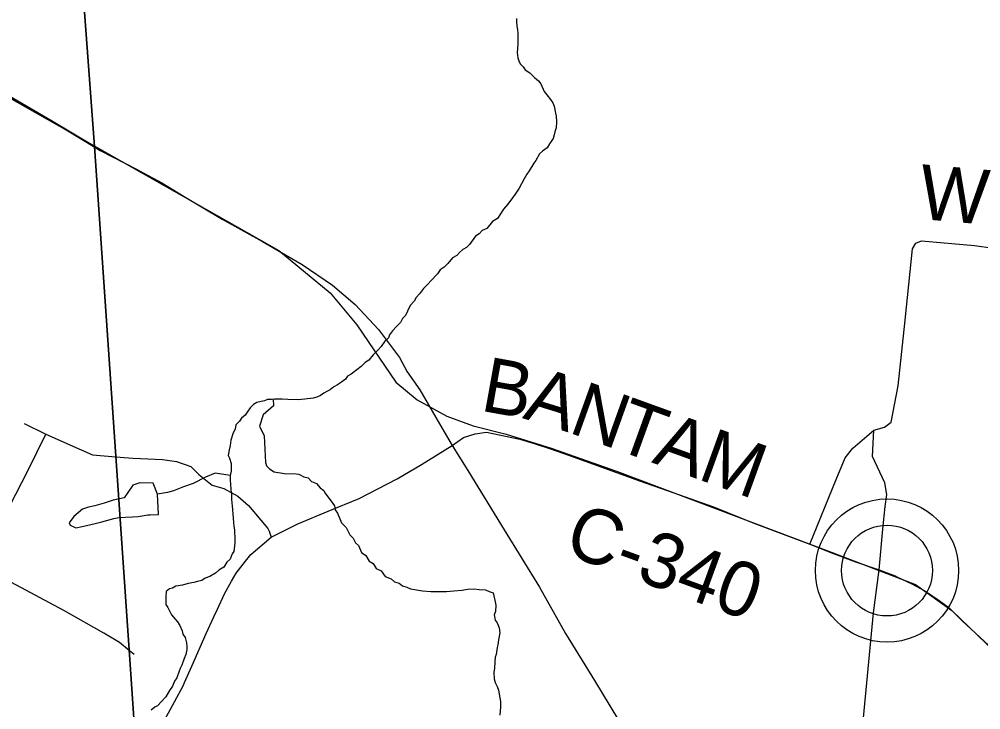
# Model space of a CAD drawing. Extents: x 0 to 39.3, y -3.9 to 22.
# Drawn here: x 7.624 to 8.623, y 16.123 to 16.84 of the extents above; entities that cross this region are included whole.
import ezdxf

# ---------------------------------------------------------------- set-up
doc = ezdxf.new("R2010")
doc.units = 0
for name, color, linetype in [('GM_X_Corporation', 7, 'Continuous'), ('GM_X_County_Road', 7, 'Continuous'), ('GM_X_County_Road_Text', 7, 'Continuous'), ('GM_X_Minor_Lake', 7, 'Continuous'), ('GM_X_Minor_River', 7, 'Continuous'), ('GM_X_Rail_Line', 7, 'Continuous'), ('GM_X_State_Route', 7, 'Continuous'), ('GM_X_Township_Road', 7, 'Continuous'), ('GM_X_Unincorporated', 7, 'Continuous'), ('GM_X_Unincorporated_Location', 7, 'Continuous')]:
    doc.layers.add(name, color=color, linetype=linetype)

msp = doc.modelspace()

# ---------------------------------------------------------------- linework, layer by layer
at = {"layer": 'GM_X_Corporation'}
for points in [[(7.60466, 16.76574), (7.6579, 16.73471), (7.70243, 16.70782), (7.66327, 17.23426), (8.7, 17.13724), (8.7, 20.7)], [(7.83678, 14.75308), (7.74674, 16.06315), (7.73835, 16.18516), (7.72454, 16.38622), (7.70243, 16.70782), (7.6579, 16.73471), (7.60466, 16.76574)]]:
    msp.add_lwpolyline(points, dxfattribs=at)
msp.add_lwpolyline([(7.89397, 13.9), (8.7, 13.9), (8.7, 17.13724), (7.66327, 17.23426), (7.70243, 16.70782), (7.72454, 16.38622), (7.73835, 16.18516), (7.74674, 16.06315), (7.83678, 14.75308), (7.8533, 14.49864), (7.86853, 14.2638)], close=True, dxfattribs=at)
at = {"layer": 'GM_X_County_Road'}
for points in [[(8.44541, 16.29495), (8.47264, 16.36211), (8.48225, 16.38452), (8.49002, 16.39458), (8.51197, 16.41333), (8.52306, 16.41653), (8.52981, 16.42157), (8.53713, 16.45953), (8.54445, 16.52768), (8.5522, 16.60154), (8.55564, 16.60753), (8.56134, 16.60981), (8.61651, 16.60523), (8.65582, 16.59954), (8.7, 16.59435)], [(8.07381, 16.39756), (8.08571, 16.40556), (8.09782, 16.40967), (8.10961, 16.41116), (8.14414, 16.40396), (8.15912, 16.39938), (8.17512, 16.39435), (8.18203, 16.39185)], [(8.51747, 16.26835), (8.52121, 16.31062), (8.5236, 16.33388), (8.52524, 16.34655), (8.52341, 16.35845), (8.5106, 16.38589), (8.51197, 16.41333)], [(8.18203, 16.39185), (8.1909, 16.38863), (8.22063, 16.37811), (8.26854, 16.3607), (8.30433, 16.34839), (8.34549, 16.33375), (8.38712, 16.31683), (8.44541, 16.29495), (8.46624, 16.28664)], [(8.46624, 16.28664), (8.49277, 16.27658), (8.51747, 16.26835), (8.53393, 16.26194), (8.53566, 16.26112)], [(8.48594, 15.95462), (8.51168, 16.22373), (8.51747, 16.26835)], [(8.53566, 16.26112), (8.55131, 16.25371), (8.56503, 16.2464), (8.57875, 16.23724), (8.58973, 16.22902), (8.60391, 16.21484), (8.63547, 16.18602), (8.7, 16.12481)]]:
    msp.add_lwpolyline(points, dxfattribs=at)
at = {"layer": 'GM_X_Minor_Lake'}
for points in [[(7.76779, 16.34686), (7.76344, 16.35834), (7.74939, 16.35858), (7.74214, 16.35605), (7.73707, 16.34854), (7.73318, 16.3429), (7.72175, 16.34044), (7.71259, 16.33756), (7.70267, 16.33469), (7.69619, 16.33329), (7.69008, 16.33111), (7.68084, 16.32367), (7.67617, 16.31691), (7.67727, 16.31461), (7.68292, 16.31185), (7.68978, 16.31325), (7.70312, 16.31643), (7.70998, 16.31822), (7.72256, 16.32142), (7.7279, 16.32246), (7.74196, 16.32336), (7.74766, 16.32364), (7.75184, 16.32433), (7.75793, 16.32536), (7.76021, 16.32532)], [(7.76021, 16.32532), (7.76908, 16.32567), (7.76779, 16.34686)]]:
    msp.add_lwpolyline(points, dxfattribs=at)
at = {"layer": 'GM_X_Minor_River'}
for points in [[(8.14079, 16.84104), (8.14074, 16.838), (8.14104, 16.83305), (8.14174, 16.82961), (8.14205, 16.82542), (8.14231, 16.81819), (8.14226, 16.81515), (8.14178, 16.80945), (8.14134, 16.80565), (8.142, 16.79994), (8.14309, 16.79688), (8.14456, 16.79381), (8.14755, 16.79071), (8.14978, 16.78763), (8.15467, 16.7845), (8.15953, 16.77947), (8.16365, 16.77597), (8.16588, 16.77289), (8.16955, 16.76522), (8.17215, 16.76175), (8.17625, 16.75673), (8.17847, 16.75327), (8.17994, 16.74982), (8.18133, 16.74257), (8.18204, 16.73951), (8.18232, 16.73342), (8.18184, 16.72734), (8.18063, 16.72318), (8.17982, 16.72015), (8.17899, 16.71636), (8.17509, 16.71072), (8.17274, 16.70658), (8.16775, 16.70324), (8.16465, 16.70025), (8.16074, 16.69348), (8.15879, 16.69047), (8.15409, 16.68256), (8.15137, 16.67918), (8.14863, 16.67429), (8.14352, 16.66449), (8.13924, 16.65847), (8.13651, 16.65472), (8.13184, 16.64795), (8.12719, 16.64271), (8.12095, 16.63331), (8.11595, 16.62997), (8.11012, 16.62285), (8.10515, 16.62065), (8.10205, 16.61728), (8.0982, 16.61468)], [(8.0982, 16.61468), (8.09197, 16.60604), (8.08888, 16.60306), (8.08504, 16.60084), (8.08196, 16.59823), (8.07886, 16.59486), (8.07425, 16.59228), (8.06959, 16.58628), (8.06573, 16.58254), (8.0615, 16.57995), (8.05877, 16.57581), (8.0518, 16.56833), (8.0487, 16.56496), (8.04406, 16.56047), (8.04016, 16.55484), (8.03668, 16.55109), (8.03433, 16.54733), (8.03046, 16.54283), (8.02769, 16.5368), (8.02534, 16.53227), (8.02225, 16.52928), (8.02028, 16.52513), (8.01602, 16.52102), (8.01215, 16.51653), (8.00904, 16.5124), (8.00784, 16.50937), (8.00398, 16.50564), (8.00009, 16.50038), (7.99698, 16.49663), (7.99195, 16.49139), (7.9873, 16.48615), (7.98346, 16.48355), (7.97959, 16.47944), (7.97497, 16.47609), (7.96919, 16.47163), (7.96535, 16.46941), (7.96302, 16.46641), (7.95916, 16.46305), (7.95494, 16.46047), (7.9511, 16.45825), (7.94763, 16.45565), (7.94072, 16.45158), (7.93726, 16.44936), (7.93343, 16.44753), (7.92961, 16.44645), (7.92085, 16.44547), (7.91399, 16.44483), (7.90335, 16.44501), (7.89728, 16.4455), (7.88929, 16.44564), (7.88625, 16.44531), (7.88206, 16.445), (7.879, 16.44392), (7.87557, 16.44322), (7.87099, 16.44215), (7.86753, 16.43993), (7.86405, 16.43657), (7.86171, 16.43319), (7.85898, 16.42905), (7.85512, 16.42569), (7.85317, 16.42268), (7.8493, 16.41895), (7.84847, 16.4144), (7.8465, 16.41063), (7.8441, 16.40306), (7.84324, 16.39737), (7.8424, 16.39282), (7.84117, 16.38714), (7.84259, 16.38406), (7.84441, 16.37883)], [(7.8882, 16.44552), (7.88844, 16.43842), (7.87764, 16.4291), (7.87371, 16.41741), (7.87879, 16.40742), (7.87991, 16.37964)], [(7.84441, 16.37883), (7.84426, 16.37083), (7.84342, 16.36628), (7.84332, 16.36095), (7.84364, 16.35752), (7.84391, 16.35143), (7.8446, 16.34723), (7.84487, 16.34114), (7.84551, 16.33427), (7.84583, 16.33122), (7.84612, 16.32589), (7.84643, 16.32246), (7.84671, 16.31674), (7.84704, 16.31407), (7.84772, 16.30949), (7.84805, 16.30682), (7.84836, 16.30263), (7.84824, 16.29616), (7.8478, 16.29312), (7.84732, 16.28742), (7.84537, 16.28479), (7.84337, 16.2795), (7.83988, 16.27613), (7.83674, 16.27086), (7.83174, 16.2679), (7.82826, 16.26491), (7.8221, 16.26121), (7.81751, 16.25976), (7.81404, 16.25716), (7.80945, 16.2561), (7.80562, 16.25502), (7.79989, 16.25398), (7.79377, 16.25218), (7.7869, 16.25115), (7.78344, 16.24931), (7.78038, 16.2486), (7.7769, 16.24562), (7.77643, 16.2403), (7.77666, 16.2323), (7.77851, 16.22922), (7.78108, 16.22423), (7.78256, 16.22154), (7.78852, 16.21421), (7.79111, 16.21035), (7.79368, 16.20498), (7.79438, 16.20154), (7.7966, 16.19808), (7.79802, 16.19235), (7.79834, 16.18891), (7.79827, 16.18549), (7.79742, 16.18018), (7.79544, 16.17602), (7.79303, 16.16921), (7.79145, 16.16581), (7.79026, 16.16317), (7.78784, 16.15598), (7.7855, 16.15259), (7.7835, 16.1473), (7.78037, 16.14278), (7.77645, 16.13638), (7.77217, 16.1315), (7.76791, 16.12701), (7.76521, 16.12554), (7.76135, 16.12256)], [(7.87991, 16.37964), (7.88098, 16.3762), (7.88435, 16.3731), (7.88925, 16.36997), (7.89987, 16.36826), (7.91205, 16.36805), (7.91471, 16.36763), (7.91999, 16.36487), (7.92453, 16.36365), (7.9279, 16.36017), (7.93318, 16.35779), (7.93691, 16.35354), (7.94067, 16.35081), (7.94176, 16.34813), (7.94734, 16.3408), (7.9518, 16.33464), (7.95248, 16.33043), (7.9547, 16.32697), (7.95909, 16.317), (7.96395, 16.31235), (7.96762, 16.30467), (7.97098, 16.30119), (7.97356, 16.2962), (7.97656, 16.29348), (7.97985, 16.28619), (7.98436, 16.28307), (7.98768, 16.2773), (7.99183, 16.27495), (7.99516, 16.26956), (8.00006, 16.26719), (8.00452, 16.26141), (8.01057, 16.25902), (8.01394, 16.25592), (8.01886, 16.25431), (8.02224, 16.25159), (8.02678, 16.25037), (8.03055, 16.2484), (8.03701, 16.24753), (8.04308, 16.24628), (8.05182, 16.24575), (8.05905, 16.24562), (8.06819, 16.24585), (8.07582, 16.24648), (8.08421, 16.2471), (8.08993, 16.24814), (8.09679, 16.2484), (8.10211, 16.24793), (8.10857, 16.24744), (8.11235, 16.24585), (8.11651, 16.24426), (8.11863, 16.23509), (8.11933, 16.23165), (8.11882, 16.22481), (8.11762, 16.2214), (8.11866, 16.21605), (8.12052, 16.21336), (8.1227, 16.20799), (8.12337, 16.20265), (8.1221, 16.19544), (8.12125, 16.19051), (8.12081, 16.18747), (8.11954, 16.18026), (8.11873, 16.17761), (8.11827, 16.17305), (8.11776, 16.16582), (8.11731, 16.16202), (8.11756, 16.15517), (8.11864, 16.15134), (8.12084, 16.14712), (8.12192, 16.14329), (8.12329, 16.13528), (8.12399, 16.13146), (8.12427, 16.12612), (8.12335, 16.11739)], [(7.84342, 16.36628), (7.82776, 16.36861), (7.81783, 16.36461), (7.80481, 16.35799), (7.79487, 16.35436), (7.78456, 16.35036), (7.77845, 16.34857), (7.76779, 16.34686)]]:
    msp.add_lwpolyline(points, dxfattribs=at)
at = {"layer": 'GM_X_Rail_Line'}
msp.add_lwpolyline([(7.57788, 16.77877), (7.89409, 16.59986), (7.94728, 16.55608), (7.97489, 16.52279), (8.01544, 16.46306), (8.0377, 16.44475), (8.06826, 16.42779), (8.09576, 16.41773), (8.13011, 16.40916), (8.17679, 16.39479), (8.24457, 16.37069), (8.46874, 16.28619), (8.55532, 16.25293), (8.59277, 16.22593), (8.7, 16.12327)], dxfattribs=at)
at = {"layer": 'GM_X_State_Route'}
for points in [[(7.4893, 16.81722), (7.51737, 16.80767), (7.53663, 16.80049), (7.56603, 16.78677), (7.60489, 16.76521), (7.65813, 16.73419), (7.70266, 16.7073), (7.70842, 16.70382), (7.74599, 16.68455), (7.75367, 16.68038)], [(7.75367, 16.68038), (7.77244, 16.67018), (7.79563, 16.65613), (7.83515, 16.63261), (7.87695, 16.6091), (7.91811, 16.58526), (7.94978, 16.56403), (7.9733, 16.54378), (7.99747, 16.51798), (8.01935, 16.48891), (8.02737, 16.47401), (8.04026, 16.45508), (8.06077, 16.42001), (8.07381, 16.39756)], [(7.79601, 16.15107), (7.80347, 16.16818), (7.81856, 16.20204), (7.8265, 16.21943), (7.83008, 16.22738), (7.83738, 16.24329), (7.84473, 16.2565), (7.84954, 16.26476), (7.85929, 16.27736), (7.865, 16.28412), (7.88604, 16.30211), (7.91357, 16.31604), (7.9453, 16.3293), (7.97746, 16.34222), (8.01675, 16.3628), (8.04226, 16.37766), (8.07381, 16.39756)], [(8.07381, 16.39756), (8.09032, 16.37156), (8.12793, 16.30965), (8.16461, 16.25032), (8.1917, 16.20198), (8.22178, 16.15321), (8.2548, 16.09881), (8.27418, 16.06819), (8.29117, 16.04668), (8.30299, 16.03576), (8.3115, 16.02725), (8.32563, 16.01439), (8.3423, 16.00261), (8.35607, 15.99391), (8.37219, 15.98485), (8.38705, 15.97834), (8.40064, 15.9729), (8.42092, 15.96601), (8.4481, 15.9604), (8.48594, 15.95462)], [(7.63346, 15.94077), (7.64241, 15.94836), (7.66403, 15.96893), (7.68759, 15.98994), (7.70785, 16.0111), (7.72556, 16.03331), (7.74043, 16.05253), (7.74697, 16.06263), (7.74958, 16.06663), (7.76143, 16.08585), (7.76924, 16.10131), (7.78562, 16.1313), (7.79483, 16.14837), (7.79601, 16.15107)]]:
    msp.add_lwpolyline(points, dxfattribs=at)
at = {"layer": 'GM_X_Township_Road'}
for p, q in [((7.62932, 16.4201), (7.65197, 16.40902)), ((7.65197, 16.40902), (7.68854, 16.393))]:
    msp.add_line(p, q, dxfattribs=at)
for points in [[(7.74383, 16.18046), (7.73859, 16.18464), (7.72842, 16.19274), (7.71223, 16.20238), (7.67051, 16.22616), (7.59123, 16.2683), (7.58619, 16.2741), (7.58908, 16.28543), (7.63318, 16.37119), (7.65197, 16.40902)], [(7.68854, 16.393), (7.70042, 16.38779), (7.72477, 16.38569), (7.73771, 16.38458)], [(7.73771, 16.38458), (7.74269, 16.38415), (7.77307, 16.38284), (7.78759, 16.38085), (7.80246, 16.37557), (7.81071, 16.36731), (7.82458, 16.35609), (7.83678, 16.35256), (7.85149, 16.3446), (7.86245, 16.335), (7.87506, 16.3197), (7.88255, 16.31128), (7.88406, 16.30858), (7.88604, 16.30211)]]:
    msp.add_lwpolyline(points, dxfattribs=at)
at = {"layer": 'GM_X_Unincorporated'}
for radius in [0.0744, 0.04716]:
    msp.add_circle((8.52559, 16.26751), radius, dxfattribs=at)
at = {"layer": 'GM_X_Unincorporated_Location'}
msp.add_line((8.52559, 16.26751), (8.52559, 16.26751), dxfattribs=at)

# ---------------------------------------------------------------- texts
at = {"layer": 'GM_X_County_Road_Text'}
for s, height, rotation, p in [('W', 0.05682, 355.06082, (8.55733, 16.63287)), ('B', 0.05682, 349.7908, (8.10206, 16.43378)), ('A', 0.05682, 342.82135, (8.14622, 16.42594)), ('N', 0.05682, 340.24424, (8.19335, 16.41139)), ('T', 0.05682, 340.085, (8.24036, 16.3945)), ('A', 0.05682, 340.08643, (8.28032, 16.38002)), ('M', 0.05682, 340.08473, (8.32733, 16.36299)), ('C-340', 0.056818, 339.94637, (8.18806, 16.28576))]:
    msp.add_text(s, height=height, rotation=rotation, dxfattribs=at).set_placement(p)

doc.saveas('drawing.dxf')
